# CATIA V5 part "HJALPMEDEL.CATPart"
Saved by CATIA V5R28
Part number: Part7
Bounding box of the stored display mesh (mm): x -42.698 to 42.698, y -42.698 to 42.698, z 0 to 10
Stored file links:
  H:\Maskiningenjör\Examensarbete\Klart\Klart & Skickas\HJALPMEDEL.CATPart
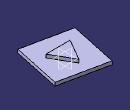
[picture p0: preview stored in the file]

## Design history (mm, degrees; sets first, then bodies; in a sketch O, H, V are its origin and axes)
Body1 (main body)
  Sketch1 on xy-plane, origin (0, 0, 0), H (1, 0, 0), V (0, 1, 0)
    construction line L1 (-36, 36) -> (36, 36)
    construction line L2 (36, 36) -> (36, -36)
    construction line L3 (36, -36) -> (-36, -36)
    construction line L4 (-36, -36) -> (-36, 36)
    line L5 (-27.7285, 42.6981) -> (-42.6981, -27.7285)
    line L6 (-42.6981, -27.7285) -> (27.7285, -42.6981)
    line L7 (27.7285, -42.6981) -> (42.6981, 27.7285)
    line L8 (42.6981, 27.7285) -> (-27.7285, 42.6981)
    construction circle A1 centre (0, 0) radius 36
    distance L1 L3 = 72
    distance L2 L4 = 72
    length L7 = 72
    length L8 = 72
    angle L8 H = 12
    horizontal: L1 H, L3 H
    vertical: L2 V, L4 V
    symmetry: L1 L3 H, L2 L4 V
    perpendicularity: L6 L5, L8 L5
    parallelism: L7 L5
    tangency: A1 L8, A1 L6, A1 L7
  Pad1: profile Sketch1, direction (0, 0, 1), length 5
  Sketch2 on end face of Pad1, origin (0, 0, 5), H (1, 0, 0), V (0, 1, 0)
    line L1 (0, 20.7575) -> (-17.9765, -10.3787)
    line L2 (-17.9765, -10.3787) -> (17.9765, -10.3787)
    line L3 (17.9765, -10.3787) -> (0, 20.7575)
    construction circle A1 centre (0, 0) radius 10.3787
    point P4 (0, 0)
    length L2 = 35.953
    length L1 = 35.953
    length L3 = 35.953
    horizontal: L2 H
    tangency: A1 L1, A1 L3, A1 L2
    coincidence: P4 O
  Pad2: profile Sketch2, direction (0, 0, 1), length 5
